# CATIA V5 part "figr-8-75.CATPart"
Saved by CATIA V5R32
Part number: Part1
Bounding box of the stored display mesh (mm): x -48 to 48, y -106.879 to 0, z -32.702 to 29.91
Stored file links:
  D:\PROJECTS\Project 2022\CATIA V5 6R 2022\Resources\Part Files\c08_catia_v5_6r2022_prt\figr-8-75.CATPart
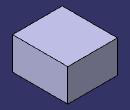
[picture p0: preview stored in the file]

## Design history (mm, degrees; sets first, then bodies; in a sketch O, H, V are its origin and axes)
Body1 (main body)
  Sketch1 on yz-plane, origin (0, 0, 0), H (0, 1, 0), V (0, 0, 1)
    line L1 (-106.8789, 29.9101) -> (0, 29.9101)
    line L2 (0, 29.9101) -> (0, -32.7018)
    line L3 (0, -32.7018) -> (-106.8789, -32.7018)
    line L4 (-106.8789, -32.7018) -> (-106.8789, 29.9101)
    point P3 (0, -32.7018)
    horizontal: L1 H, L3 H
    vertical: L2 V, L4 V
    coincidence: P3 V
  Pad1: profile Sketch1, direction (1, 0, 0), length 48, mirrored extent
Body2
  Sketch2 on yz-plane, origin (0, 0, 0), H (0, 1, 0), V (0, 0, 1)
    line L1 (30, 10) -> (90, 10)
    line L2 (90, 10) -> (90, -10)
    line L3 (90, -10) -> (30, -10)
    line L4 (30, -10) -> (30, 10)
    horizontal: L1 H, L3 H
    vertical: L2 V, L4 V
  Pad2: profile Sketch2, direction (1, 0, 0), length 26, mirrored extent
  Trim1: faces to remove face of Pad2 from Sketch2.L1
